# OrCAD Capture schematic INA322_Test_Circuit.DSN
size A; title: INA322, microPower, Single-Supply, CMOS; rev: 1.1; note: Datasheet : SBOS174B  EVM : NA; note: Reference
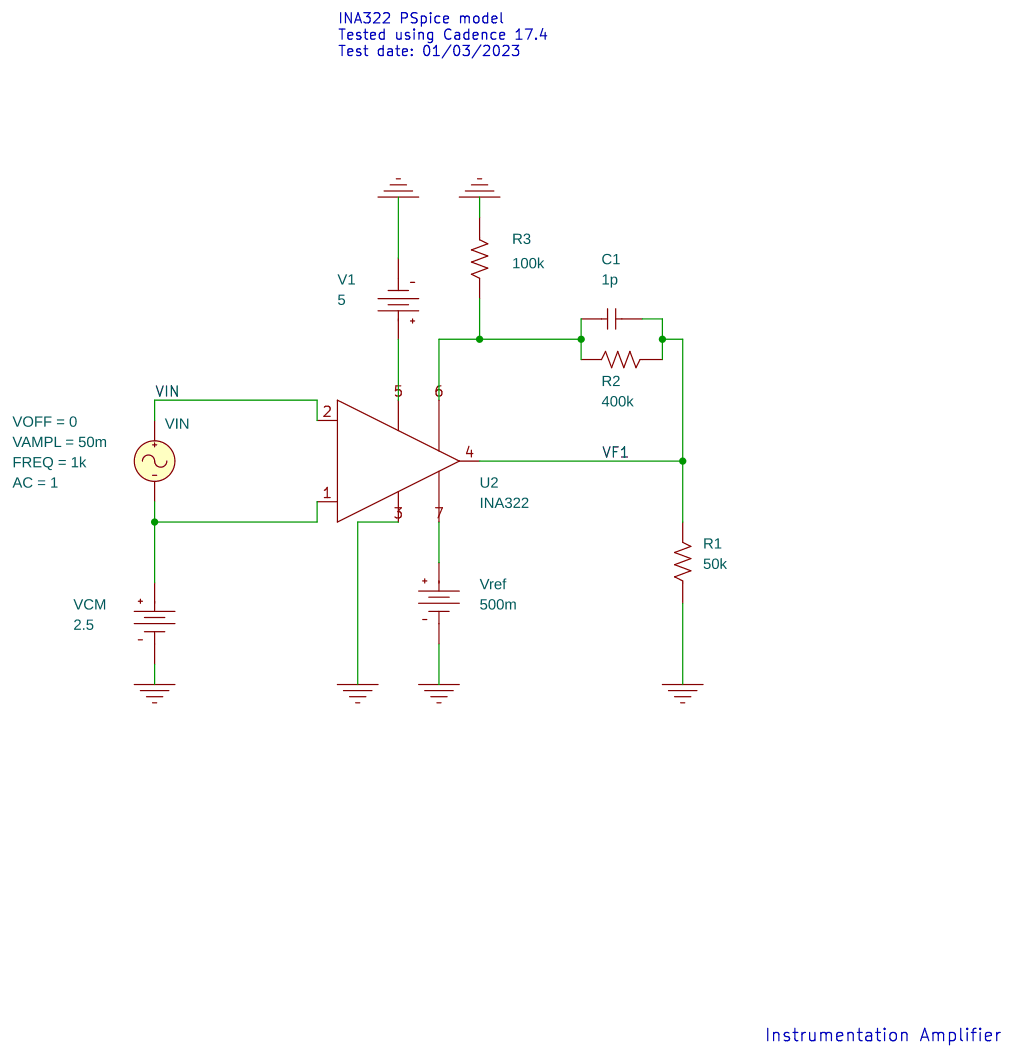
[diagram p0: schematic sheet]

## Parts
C1  1p  [RAD/CK05]
R1  50k  [AX/RC05]
R2  400k  [AX/RC05]
R3  100k  [AX/RC05]
U2  INA322
V1  VDC
VCM  VDC
VIN  VSIN
Vref  VDC

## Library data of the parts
C1 = C
R1-R3 = R
U2 = INA322
V1 = VDC: DC: 5
VCM = VDC: DC: 2.5
VIN = VSIN: AC: 1; FREQ: 1k; VAMPL: 50m; VOFF: 0
Vref = VDC: DC: 500m

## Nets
VIN: U2.2(-) VIN.1(+)
0: R1.1 R3.1 U2.3(V-) V1.1(-) VCM.1(-) Vref.1(-)
VF1: C1.2 R1.2 R2.1 U2.4(OUT)
N01574: U2.1(+) VCM.0(+) VIN.2(-)
N14287329: C1.1 R2.2 R3.2 U2.6(RG)
N14288518: U2.7(REF) Vref.0(+)
N14292365: U2.5(V+) V1.0(+)

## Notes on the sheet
- INA322 PSpice model
  Tested using Cadence 17.4
  Test date: 01/03/2023
- Instrumentation Amplifier
